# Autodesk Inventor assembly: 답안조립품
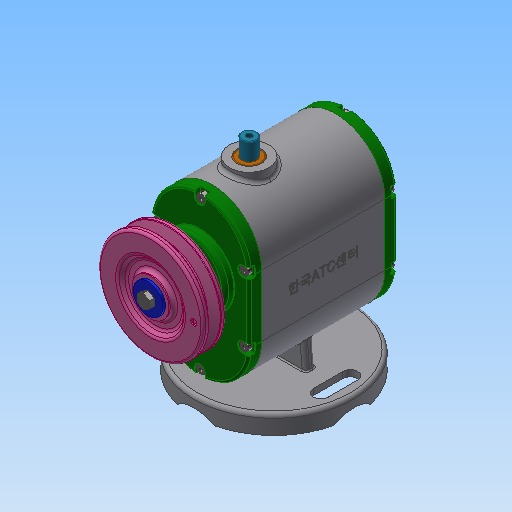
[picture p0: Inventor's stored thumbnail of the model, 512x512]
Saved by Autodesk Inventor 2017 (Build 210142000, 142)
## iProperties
Part Number: 답안조립품
Material: 일반
Document SubType Name: Assembly
Designer: user
Author: user
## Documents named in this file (19)
- C:\Users\user\Desktop\611006V1007\답안조립품.iam
- C:\Users\user\Desktop\611006V1007\본체.ipt
- C:\Users\user\Desktop\611006V1007\V-벨트풀리.ipt
- C:\Users\user\Desktop\611006V1007\가변스프링.ipt
- C:\Users\user\Desktop\611006V1007\뒤커버.ipt
- C:\Users\user\Desktop\611006V1007\멈춤나사 M3.ipt
- C:\Users\user\Desktop\611006V1007\메인축.ipt
- C:\Users\user\Desktop\611006V1007\베어링 608.ipt
- C:\Users\user\Desktop\611006V1007\베어링 6003.ipt
- C:\Users\user\Desktop\611006V1007\볼트 M4.ipt
- C:\Users\user\Desktop\611006V1007\볼트 M6.ipt
- C:\Users\user\Desktop\611006V1007\부시.ipt
- C:\Users\user\Desktop\611006V1007\서브축.ipt
- C:\Users\user\Desktop\611006V1007\슬라이더.ipt
- C:\Users\user\Desktop\611006V1007\앞커버.ipt
- C:\Users\user\Desktop\611006V1007\오일실 8x22x7.ipt
- C:\Users\user\Desktop\611006V1007\오일실 17x32x8.ipt
- C:\Users\user\Desktop\611006V1007\와셔.ipt
- C:\Users\user\Desktop\611006V1007\키 5x5.ipt
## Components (2 placed, 2 different names)
1. V-벨트풀리:1
2. 가변스프링:1
